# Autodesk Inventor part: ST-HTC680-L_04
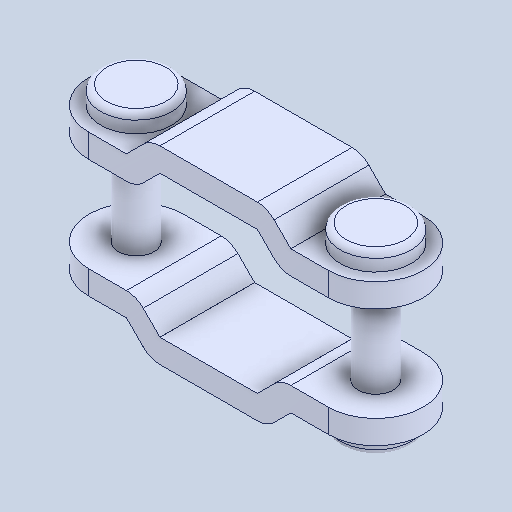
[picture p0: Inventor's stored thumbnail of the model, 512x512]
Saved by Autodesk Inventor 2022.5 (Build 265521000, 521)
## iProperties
Created: 2024-07
Part Number: ST-HTC680-L_04
Material: 一般
Document SubType Name: Modeling
Designer: ImaoCorp
Density: 1 g/cm^3
Appearance: 既定
Author: ImaoCorp
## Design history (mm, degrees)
feature "ST-HTC680-L_04"
node "ソリッド1"
